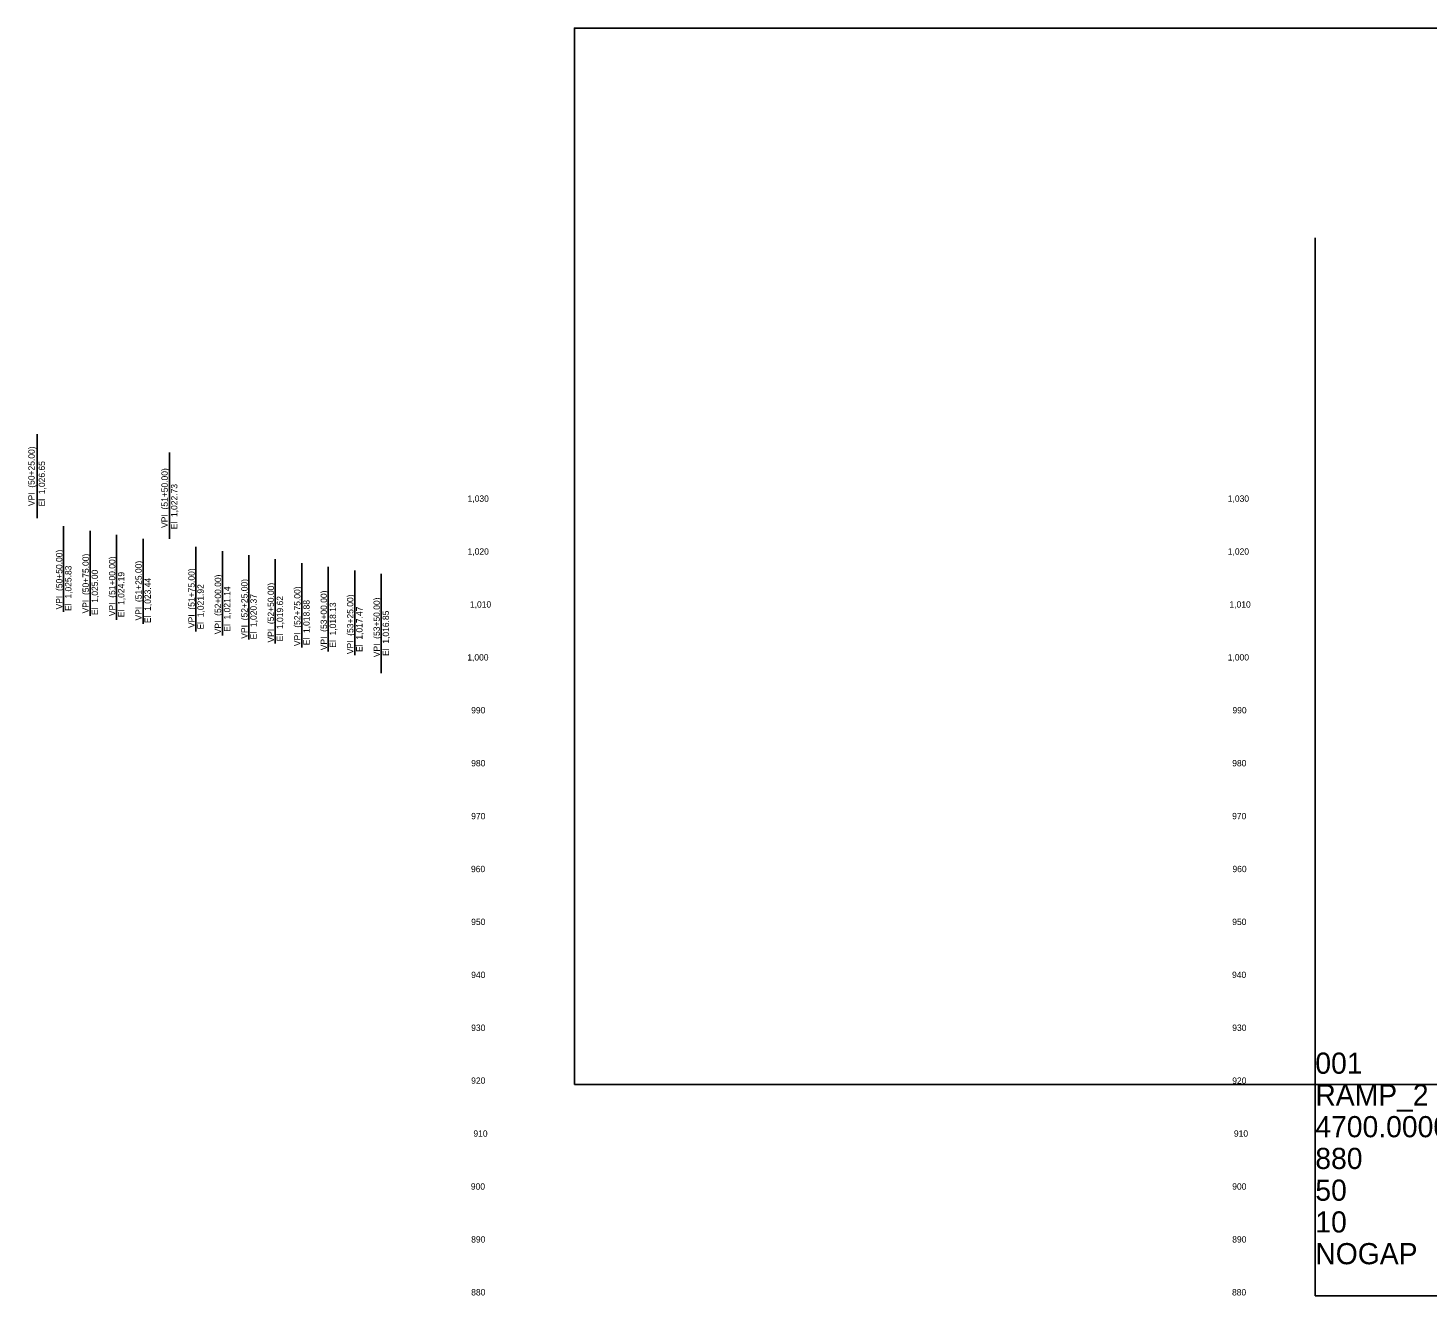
# Model space of a CAD drawing. Extents: x 1608399 to 16975600, y 1093178 to 12565486.
# Drawn here: x 16971804 to 16973126, y 12564288 to 12565486 of the extents above; entities that cross this region are included whole.
import ezdxf

# ---------------------------------------------------------------- set-up
doc = ezdxf.new("R2010")
doc.units = 0
for name, color, linetype in [('Default', 7, 'Continuous'), ('RD_DDB_ElevTX', 7, 'Continuous'), ('RD_DDB_PI', 7, 'Continuous'), ('RD_GPK_Profile_Cell', 7, 'Continuous')]:
    doc.layers.add(name, color=color, linetype=linetype)

msp = doc.modelspace()

# ---------------------------------------------------------------- linework, layer by layer
at = {"layer": 'Default'}
msp.add_lwpolyline([(16972319.9, 12564487.8), (16973819.9, 12564487.8), (16973819.9, 12565486), (16972319.9, 12565486)], close=True, dxfattribs=at)
at = {"layer": 'RD_DDB_PI'}
for p, q in [((16971812.2, 12565022.8), (16971812.2, 12565102.2)), ((16971937.2, 12565003.2), (16971937.2, 12565084.8)), ((16971837.2, 12564934.3), (16971837.2, 12565015.2)), ((16971862.2, 12564930.6), (16971862.2, 12565011)), ((16971887.2, 12564926.9), (16971887.2, 12565007)), ((16971912.2, 12564923.1), (16971912.2, 12565003.2)), ((16971962.2, 12564915.6), (16971962.2, 12564995.6)), ((16971987.2, 12564911.9), (16971987.2, 12564991.7)), ((16972012.2, 12564908.1), (16972012.2, 12564987.9)), ((16972037.2, 12564904.4), (16972037.2, 12564984.1)), ((16972062.2, 12564900.6), (16972062.2, 12564980.4)), ((16972087.2, 12564896.9), (16972087.2, 12564976.7)), ((16972112.2, 12564893.2), (16972112.2, 12564973.4)), ((16972137.2, 12564876.5), (16972137.2, 12564970.3))]:
    msp.add_line(p, q, dxfattribs=at)
at = {"layer": 'RD_GPK_Profile_Cell'}
for q in [(16973019.9, 12565287.8), (16975092.9, 12564287.8), (16973019.9, 12564287.8)]:
    msp.add_line((16973019.9, 12564287.8), q, dxfattribs=at)

# ---------------------------------------------------------------- texts
at = {"layer": 'RD_DDB_ElevTX'}
for s, p in [('1,030', (16972218.9, 12565038.3)), ('1,030', (16972937.2, 12565038.3)), ('1,030', (16972937.2, 12565038.3)), ('1,020', (16972218.9, 12564988.3)), ('1,020', (16972937.2, 12564988.3)), ('1,020', (16972937.2, 12564988.3)), ('1,010', (16972221.1, 12564938.3)), ('1,010', (16972938.8, 12564938.3)), ('1,010', (16972938.8, 12564938.3)), ('1,000', (16972218.6, 12564888.3)), ('1,000', (16972937.2, 12564888.3)), ('1,000', (16972937.2, 12564888.3)), ('990', (16972222.3, 12564838.3)), ('990', (16972941.6, 12564838.3)), ('990', (16972941.6, 12564838.3)), ('980', (16972222.3, 12564788.3)), ('980', (16972941.4, 12564788.3)), ('980', (16972941.4, 12564788.3)), ('970', (16972222.3, 12564738.3)), ('970', (16972941.3, 12564738.3)), ('970', (16972941.3, 12564738.3)), ('960', (16972222.1, 12564688.3)), ('960', (16972941.6, 12564688.3)), ('960', (16972941.6, 12564688.3)), ('950', (16972222.3, 12564638.3)), ('950', (16972941.4, 12564638.3)), ('950', (16972941.4, 12564638.3)), ('940', (16972222.3, 12564588.3)), ('940', (16972941.2, 12564588.3)), ('940', (16972941.2, 12564588.3)), ('930', (16972222.3, 12564538.3)), ('930', (16972941.4, 12564538.3)), ('930', (16972941.4, 12564538.3)), ('920', (16972222.3, 12564488.3)), ('920', (16972941.4, 12564488.3)), ('920', (16972941.4, 12564488.3)), ('910', (16972224.4, 12564438.3)), ('910', (16972943, 12564438.3)), ('910', (16972943, 12564438.3)), ('900', (16972222, 12564388.3)), ('900', (16972941.4, 12564388.3)), ('900', (16972941.4, 12564388.3)), ('890', (16972222.3, 12564338.3)), ('890', (16972941.4, 12564338.3)), ('890', (16972941.4, 12564338.3)), ('880', (16972222.3, 12564288.3)), ('880', (16972941.2, 12564288.3)), ('880', (16972941.2, 12564288.3))]:
    msp.add_text(s, height=6, dxfattribs=at).set_placement(p)
at = {"layer": 'RD_DDB_PI'}
for s, p in [('VPI  (50+25.00)', (16971809.8, 12565034.2)), ('El  1,026.65', (16971819.6, 12565033.9)), ('VPI  (51+50.00)', (16971935.6, 12565013.6)), ('El  1,022.73', (16971944.7, 12565012.3)), ('VPI  (50+50.00)', (16971836, 12564936.6)), ('VPI  (50+75.00)', (16971861, 12564932.8)), ('VPI  (51+00.00)', (16971886, 12564930.2)), ('VPI  (51+25.00)', (16971911, 12564926.1)), ('El  1,025.83', (16971844.6, 12564935.2)), ('El  1,025.00', (16971869.6, 12564931.3)), ('El  1,024.19', (16971894.6, 12564929.2)), ('VPI  (51+75.00)', (16971961, 12564919)), ('VPI  (52+00.00)', (16971986, 12564913.1)), ('El  1,023.44', (16971919.6, 12564923.6)), ('El  1,021.92', (16971969.6, 12564917.6)), ('El  1,021.14', (16971994.6, 12564915.5)), ('VPI  (52+25.00)', (16972011, 12564908.9)), ('VPI  (52+50.00)', (16972036, 12564905.3)), ('VPI  (52+75.00)', (16972061, 12564901.9)), ('El  1,020.37', (16972019.6, 12564908.3)), ('El  1,019.62', (16972044.6, 12564906.4)), ('El  1,018.88', (16972069.6, 12564902.7)), ('VPI  (53+00.00)', (16972086, 12564898)), ('El  1,018.13', (16972094.6, 12564900.4)), ('VPI  (53+25.00)', (16972111, 12564894.3)), ('VPI  (53+50.00)', (16972136, 12564891.4)), ('El  1,017.47', (16972119.6, 12564896.4)), ('El  1,016.85', (16972144.6, 12564892.6))]:
    msp.add_text(s, height=6, rotation=90, dxfattribs=at).set_placement(p)
at = {"layer": 'RD_GPK_Profile_Cell'}
for s, p in [('001', (16973019.9, 12564497.8)), ('RAMP_2', (16973019.9, 12564467.8)), ('4700.000000', (16973019.9, 12564437.8)), ('880', (16973019.9, 12564407.8)), ('50', (16973019.9, 12564377.8)), ('10', (16973019.9, 12564347.8)), ('NOGAP', (16973019.9, 12564317.8))]:
    msp.add_text(s, height=20, dxfattribs=at).set_placement(p)

doc.saveas('drawing.dxf')
